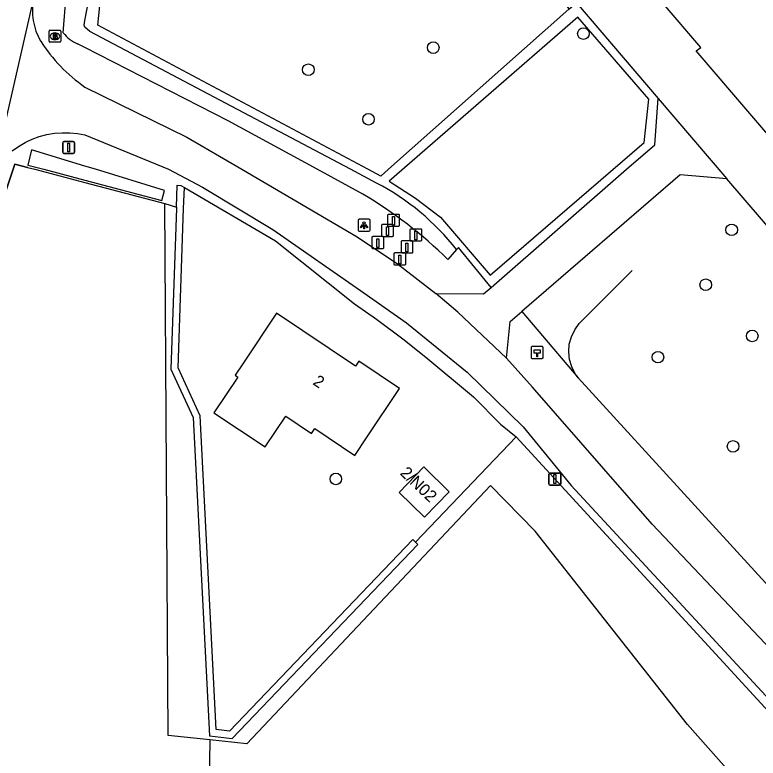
# Model space of a CAD drawing. Extents: x 160203 to 161526, y 379529 to 381797.
# Drawn here: x 160994.1 to 161056.6, y 381200.5 to 381263 of the extents above; entities that cross this region are included whole.
import ezdxf

# ---------------------------------------------------------------- set-up
doc = ezdxf.new("R2010")
doc.units = 0
for name, color, linetype in [('IMGEO_Boom', 7, 'Continuous'), ('IMGEO_Bouwland', 7, 'Continuous'), ('IMGEO_Brandkraan', 7, 'Continuous'), ('IMGEO_Grasland_agrarisch', 7, 'Continuous'), ('IMGEO_Grasland_overig', 7, 'Continuous'), ('IMGEO_Groenvoorziening', 7, 'Continuous'), ('IMGEO_Haag', 7, 'Continuous'), ('IMGEO_Hectometerpaal', 7, 'Continuous'), ('IMGEO_Hek', 7, 'Continuous'), ('IMGEO_Inrit_open', 7, 'Continuous'), ('IMGEO_Lichtpunt', 7, 'Continuous'), ('IMGEO_Loofbos', 7, 'Continuous'), ('IMGEO_Paal', 7, 'Continuous'), ('IMGEO_Pand', 7, 'Continuous'), ('IMGEO_Pand_nummerreeks', 7, 'Continuous'), ('IMGEO_Rijbaan_lokaal_gesloten', 7, 'Continuous'), ('IMGEO_Verkeersbordpaal', 7, 'Continuous'), ('IMGEO_Waterloop', 7, 'Continuous')]:
    doc.layers.add(name, color=color, linetype=linetype)

msp = doc.modelspace()

# ---------------------------------------------------------------- linework, layer by layer
at = {"layer": 'IMGEO_Boom'}
for centre in [(161041.928, 381261.416), (161029.301, 381260.235), (161018.79, 381258.378), (161023.851, 381254.21), (161054.398, 381244.908), (161052.216, 381240.288), (161056.13, 381235.981), (161048.198, 381234.197), (161054.516, 381226.691), (161021.103, 381223.95)]:
    msp.add_circle(centre, 0.489, dxfattribs=at)
at = {"layer": 'IMGEO_Bouwland'}
for points in [[(161010.972, 381081.302), (161010.953, 381074.647), (161003.548, 381076.227), (161000, 381077.092), (160995.21, 381078.26), (160994.378, 381077.678), (160975.971, 381079.297), (160943.925, 381083.756), (160939.305, 381085.021), (160993.954, 381250), (160994.1, 381250.44), (160995.157, 381250.162), (160995.774, 381250), (161000, 381248.889), (161006.713, 381247.124)], [(161010.514, 381202.004), (161010.411, 381196.554)]]:
    msp.add_lwpolyline(points, dxfattribs=at)
at = {"layer": 'IMGEO_Brandkraan'}
for p, q in [((160997.05, 381261.695), (160997.902, 381261.695)), ((160996.975, 381260.769), (160996.975, 381261.621)), ((160997.463, 381261.475), (160997.488, 381261.475)), ((160997.976, 381261.621), (160997.976, 381260.769)), ((160997.902, 381260.695), (160997.05, 381260.695)), ((160997.486, 381260.915), (160997.461, 381260.915))]:
    msp.add_line(p, q, dxfattribs=at)
for points in [[(160997.05, 381261.695), (160997.902, 381261.695)], [(160996.975, 381260.769), (160996.975, 381261.621)], [(160997.323, 381261.395), (160997.323, 381260.995), (160997.536, 381260.995)], [(160997.554, 381261.395), (160997.323, 381261.395)], [(160997.502, 381261.314), (160997.448, 381261.314), (160997.448, 381261.238)], [(160997.448, 381261.238), (160997.501, 381261.238)], [(160997.51, 381261.162), (160997.448, 381261.162), (160997.448, 381261.081)], [(160997.448, 381261.081), (160997.51, 381261.081)], [(160997.976, 381261.621), (160997.976, 381260.769)], [(160997.902, 381260.695), (160997.05, 381260.695)]]:
    msp.add_lwpolyline(points, dxfattribs=at)
for centre, radius, start, end in [((160997.052, 381261.619), 0.0765, 91.55205, 178.44795), ((160997.052, 381261.619), 0.0765, 91.55205, 178.44795), ((160997.9, 381261.619), 0.0765, 1.55205, 88.44795), ((160997.9, 381261.619), 0.0765, 1.55205, 88.44795), ((160997.503, 381261.276), 0.0379, 267.82845, 90.93552), ((160997.511, 381261.121), 0.0404, 269.87594, 90.50774), ((160997.558, 381261.25), 0.145, 59.4692, 91.53667), ((160997.583, 381261.297), 0.0922, 285.51372, 58.15012), ((160997.588, 381261.105), 0.105, 301.31148, 78.98903), ((160997.052, 381260.771), 0.0765, 181.55205, 268.44795), ((160997.052, 381260.771), 0.0765, 181.55205, 268.44795), ((160997.542, 381261.246), 0.251, 268.66757, 293.53466), ((160997.9, 381260.771), 0.0765, 271.55205, 358.44795), ((160997.9, 381260.771), 0.0765, 271.55205, 358.44795)]:
    msp.add_arc(centre, radius, start, end, dxfattribs=at)
for centre, major_axis, ratio, start_param, end_param in [((160997.462, 381261.195), (-0.387, 0.002), 0.722429, 4.712389, 7.853982), ((160997.487, 381261.195), (-0.39, 0.002), 0.717154, 1.570796, 4.712389)]:
    msp.add_ellipse(centre, major_axis=major_axis, ratio=ratio, start_param=start_param, end_param=end_param, dxfattribs=at)
at = {"layer": 'IMGEO_Grasland_agrarisch'}
msp.add_lwpolyline([(161040.704, 381263.465), (161025.539, 381250), (161024.88, 381249.415), (161023.785, 381250), (161001.07, 381262.141), (161001.418, 381265.417), (161003.032, 381274.033), (161003.367, 381284.915), (161005.086, 381286.001)], dxfattribs=at)
at = {"layer": 'IMGEO_Grasland_overig'}
msp.add_lwpolyline([(161036.736, 381238.047), (161041.491, 381232.447), (161060.216, 381211.973)], dxfattribs=at)
at = {"layer": 'IMGEO_Groenvoorziening'}
for points in [[(161040.704, 381263.465), (161041.339, 381264.007), (161048.214, 381255.953)], [(161047.031, 381252.253), (161047.443, 381255.899), (161041.46, 381262.811), (161025.599, 381249.008), (161027.816, 381247.584), (161029.904, 381245.979), (161034.072, 381241.099), (161047.031, 381252.253)], [(161081.374, 381241.599), (161083.542, 381239.045), (161074.732, 381231.273), (161073.023, 381233.247), (161069.952, 381230.624), (161053.998, 381249.187)], [(161008.358, 381248.475), (161016.014, 381243.993), (161022.676, 381238.69), (161024.528, 381237.381), (161026.738, 381235.726), (161028.679, 381234.184), (161032.692, 381230.87), (161034.943, 381228.573), (161036.267, 381227.494)], [(161034.16, 381240.067), (161031.419, 381243.429), (161031.254, 381243.257)]]:
    msp.add_lwpolyline(points, dxfattribs=at)
at = {"layer": 'IMGEO_Haag'}
for points in [[(161007.701, 381246.818), (161007.764, 381248.657), (161008.064, 381248.647), (161008.358, 381248.475)], [(161027.792, 381218.641), (161027.575, 381218.848), (161012.159, 381202.744), (161011.042, 381202.875), (161009.7, 381229.266), (161007.833, 381233.298), (161008.298, 381246.716), (161008.358, 381248.475)], [(161007.701, 381246.818), (161007.698, 381246.736), (161007.229, 381233.176), (161009.107, 381229.12), (161010.468, 381202.339), (161012.385, 381202.114), (161028.008, 381218.433), (161027.792, 381218.641)]]:
    msp.add_lwpolyline(points, dxfattribs=at)
at = {"layer": 'IMGEO_Hectometerpaal'}
for p, q in [((161037.533, 381235.009), (161037.533, 381234.168)), ((161037.533, 381235.009), (161037.533, 381234.168)), ((161038.449, 381235.093), (161037.608, 381235.093)), ((161038.449, 381235.093), (161037.608, 381235.093)), ((161038.533, 381234.177), (161038.533, 381235.018)), ((161038.533, 381234.177), (161038.533, 381235.018)), ((161037.617, 381234.093), (161038.458, 381234.093)), ((161037.617, 381234.093), (161038.458, 381234.093))]:
    msp.add_line(p, q, dxfattribs=at)
msp.add_lwpolyline([(161038.058, 381234.237), (161037.998, 381234.237), (161037.998, 381234.542), (161037.778, 381234.542), (161037.778, 381234.811), (161038.278, 381234.811), (161038.278, 381234.542), (161038.058, 381234.542), (161038.058, 381234.237)], dxfattribs=at)
for centre, start, end in [((161037.611, 381235.015), 92.4484, 184.28452), ((161037.611, 381235.015), 92.4484, 184.28452), ((161038.455, 381235.015), 2.4484, 94.28452), ((161038.455, 381235.015), 2.4484, 94.28452), ((161038.455, 381234.171), 272.4484, 4.28452), ((161038.455, 381234.171), 272.4484, 4.28452), ((161037.611, 381234.171), 182.4484, 274.28452), ((161037.611, 381234.171), 182.4484, 274.28452)]:
    msp.add_arc(centre, 0.0779, start, end, dxfattribs=at)
at = {"layer": 'IMGEO_Hek'}
for points in [[(161024.88, 381249.415), (161023.785, 381250), (161001.07, 381262.141), (161001.418, 381265.417), (161003.032, 381274.033), (161003.367, 381284.915), (161005.086, 381286.001)], [(161041.952, 381266.885), (161039.801, 381264.963), (161040.704, 381263.465), (161025.539, 381250), (161024.88, 381249.415)], [(160995.157, 381250.162), (160994.1, 381250.44), (160993.954, 381250), (160939.305, 381085.021), (160943.925, 381083.756), (160975.971, 381079.297), (160994.378, 381077.678), (160995.21, 381078.26), (161000, 381077.092), (161003.548, 381076.227), (161010.953, 381074.647)], [(161008.064, 381248.647), (161008.358, 381248.475), (161016.014, 381243.993), (161022.676, 381238.69), (161024.528, 381237.381), (161026.738, 381235.726), (161028.679, 381234.184), (161032.692, 381230.87), (161034.943, 381228.573), (161036.267, 381227.494)], [(161041.491, 381232.447), (161041.237, 381232.798), (161040.941, 381233.375), (161040.757, 381233.997), (161040.69, 381234.642), (161040.742, 381235.288), (161040.913, 381235.914), (161041.196, 381236.497), (161041.581, 381237.019), (161046.025, 381241.49)], [(161036.267, 381227.494), (161059.702, 381201.99), (161062.8, 381198.618), (161073.827, 381188.007), (161074.485, 381187.273), (161075.831, 381185.995), (161077.303, 381184.864), (161078.885, 381183.893), (161080.56, 381183.093), (161082.31, 381182.472), (161085.055, 381181.736)]]:
    msp.add_lwpolyline(points, dxfattribs=at)
at = {"layer": 'IMGEO_Inrit_open'}
for points in [[(161034.16, 381240.067), (161045.56, 381250), (161047.935, 381252.069), (161048.214, 381255.953)], [(161048.214, 381255.953), (161053.998, 381249.187)], [(161053.998, 381249.187), (161050.077, 381249.546), (161036.736, 381238.047)], [(161029.512, 381239.55), (161033.525, 381239.513), (161034.16, 381240.067)], [(161035.453, 381234.099), (161035.763, 381237.208), (161036.736, 381238.047)]]:
    msp.add_lwpolyline(points, dxfattribs=at)
at = {"layer": 'IMGEO_Lichtpunt'}
for p, q in [((161022.983, 381245.698), (161022.983, 381244.891)), ((161022.983, 381245.698), (161022.983, 381244.891)), ((161023.885, 381245.793), (161023.077, 381245.793)), ((161023.885, 381245.793), (161023.077, 381245.793)), ((161023.979, 381244.891), (161023.979, 381245.698)), ((161023.979, 381244.891), (161023.979, 381245.698)), ((161023.077, 381244.797), (161023.885, 381244.797)), ((161023.077, 381244.797), (161023.885, 381244.797))]:
    msp.add_line(p, q, dxfattribs=at)
for points in [[(161023.357, 381245.362), (161023.396, 381245.334), (161023.208, 381245.072), (161023.17, 381245.099), (161023.357, 381245.362)], [(161023.459, 381245.314), (161023.506, 381245.314), (161023.506, 381244.992), (161023.459, 381244.992), (161023.459, 381245.314)], [(161023.569, 381245.334), (161023.607, 381245.361), (161023.794, 381245.099), (161023.755, 381245.071), (161023.569, 381245.334)]]:
    msp.add_lwpolyline(points, dxfattribs=at)
msp.add_circle((161023.482, 381245.496), 0.0994, dxfattribs=at)
for centre, start, end in [((161023.077, 381245.698), 90, 180), ((161023.077, 381245.698), 90, 180), ((161023.885, 381245.698), 0, 90), ((161023.885, 381245.698), 0, 90), ((161023.077, 381244.891), 180, 270), ((161023.077, 381244.891), 180, 270), ((161023.885, 381244.891), 270, 0), ((161023.885, 381244.891), 270, 360)]:
    msp.add_arc(centre, 0.0946, start, end, dxfattribs=at)
at = {"layer": 'IMGEO_Loofbos'}
for points in [[(161006.713, 381247.124), (161007.701, 381246.818)], [(161010.514, 381202.004), (161007.008, 381202.372), (161006.713, 381247.124)], [(161036.267, 381227.494), (161027.792, 381218.641)], [(161036.267, 381227.494), (161059.702, 381201.99), (161062.8, 381198.618), (161073.827, 381188.007), (161074.485, 381187.273), (161075.831, 381185.995), (161077.303, 381184.864), (161078.885, 381183.893), (161080.56, 381183.093), (161082.31, 381182.472), (161085.055, 381181.736)], [(161082.58, 381175.752), (161077.672, 381178.299), (161070.576, 381182.79), (161061.577, 381191.025), (161050.681, 381203.282), (161037.868, 381219.565), (161034.126, 381223.392), (161013.621, 381201.677), (161010.514, 381202.004)]]:
    msp.add_lwpolyline(points, dxfattribs=at)
at = {"layer": 'IMGEO_Paal'}
for p, q in [((161025.454, 381246.125), (161025.454, 381245.284)), ((161025.454, 381246.125), (161025.454, 381245.284)), ((161026.37, 381246.209), (161025.529, 381246.209)), ((161026.37, 381246.209), (161025.529, 381246.209)), ((161026.454, 381245.293), (161026.454, 381246.134)), ((161026.454, 381245.293), (161026.454, 381246.134)), ((161024.95, 381245.276), (161024.95, 381244.435)), ((161024.95, 381245.276), (161024.95, 381244.435)), ((161025.866, 381245.36), (161025.025, 381245.36)), ((161025.866, 381245.36), (161025.025, 381245.36)), ((161025.538, 381245.209), (161026.379, 381245.209)), ((161025.538, 381245.209), (161026.379, 381245.209)), ((161025.95, 381244.444), (161025.95, 381245.285)), ((161025.95, 381244.444), (161025.95, 381245.285)), ((161027.335, 381244.893), (161027.335, 381244.052)), ((161027.335, 381244.893), (161027.335, 381244.052)), ((161028.251, 381244.977), (161027.41, 381244.977)), ((161028.251, 381244.977), (161027.41, 381244.977)), ((161028.335, 381244.061), (161028.335, 381244.902)), ((161028.335, 381244.061), (161028.335, 381244.902)), ((161024.135, 381244.256), (161024.135, 381243.415)), ((161024.135, 381244.256), (161024.135, 381243.415)), ((161025.051, 381244.34), (161024.21, 381244.34)), ((161025.051, 381244.34), (161024.21, 381244.34)), ((161025.034, 381244.36), (161025.875, 381244.36)), ((161025.034, 381244.36), (161025.875, 381244.36)), ((161025.135, 381243.424), (161025.135, 381244.265)), ((161025.135, 381243.424), (161025.135, 381244.265)), ((161026.588, 381243.893), (161026.588, 381243.052)), ((161026.588, 381243.893), (161026.588, 381243.052)), ((161027.504, 381243.977), (161026.663, 381243.977)), ((161027.504, 381243.977), (161026.663, 381243.977)), ((161027.419, 381243.977), (161028.26, 381243.977)), ((161027.419, 381243.977), (161028.26, 381243.977)), ((161027.588, 381243.061), (161027.588, 381243.902)), ((161027.588, 381243.061), (161027.588, 381243.902)), ((161024.219, 381243.34), (161025.06, 381243.34)), ((161024.219, 381243.34), (161025.06, 381243.34)), ((161026.901, 381242.961), (161026.06, 381242.961)), ((161026.901, 381242.961), (161026.06, 381242.961)), ((161026.672, 381242.977), (161027.513, 381242.977)), ((161026.672, 381242.977), (161027.513, 381242.977)), ((161025.985, 381242.877), (161025.985, 381242.036)), ((161025.985, 381242.877), (161025.985, 381242.036)), ((161026.985, 381242.045), (161026.985, 381242.886)), ((161026.985, 381242.045), (161026.985, 381242.886)), ((161026.069, 381241.961), (161026.91, 381241.961)), ((161026.069, 381241.961), (161026.91, 381241.961))]:
    msp.add_line(p, q, dxfattribs=at)
for points in [[(161025.869, 381246.022), (161026.029, 381246.022), (161026.029, 381245.289), (161025.869, 381245.289), (161025.869, 381246.022)], [(161025.365, 381245.173), (161025.525, 381245.173), (161025.525, 381244.44), (161025.365, 381244.44), (161025.365, 381245.173)], [(161027.75, 381244.79), (161027.91, 381244.79), (161027.91, 381244.057), (161027.75, 381244.057), (161027.75, 381244.79)], [(161024.55, 381244.153), (161024.71, 381244.153), (161024.71, 381243.42), (161024.55, 381243.42), (161024.55, 381244.153)], [(161027.003, 381243.79), (161027.163, 381243.79), (161027.163, 381243.057), (161027.003, 381243.057), (161027.003, 381243.79)], [(161026.4, 381242.774), (161026.56, 381242.774), (161026.56, 381242.041), (161026.4, 381242.041), (161026.4, 381242.774)]]:
    msp.add_lwpolyline(points, dxfattribs=at)
for centre, start, end in [((161025.532, 381246.131), 92.4484, 184.28452), ((161025.532, 381246.131), 92.4484, 184.28452), ((161026.376, 381246.131), 2.4484, 94.28452), ((161026.376, 381246.131), 2.4484, 94.28452), ((161025.028, 381245.282), 92.4484, 184.28452), ((161025.028, 381245.282), 92.4484, 184.28452), ((161025.532, 381245.287), 182.4484, 274.28452), ((161025.532, 381245.287), 182.4484, 274.28452), ((161025.872, 381245.282), 2.4484, 94.28452), ((161025.872, 381245.282), 2.4484, 94.28452), ((161026.376, 381245.287), 272.4484, 4.28452), ((161026.376, 381245.287), 272.4484, 4.28452), ((161027.413, 381244.899), 92.4484, 184.28452), ((161027.413, 381244.899), 92.4484, 184.28452), ((161028.257, 381244.899), 2.4484, 94.28452), ((161028.257, 381244.899), 2.4484, 94.28452), ((161024.213, 381244.262), 92.4484, 184.28452), ((161024.213, 381244.262), 92.4484, 184.28452), ((161025.028, 381244.438), 182.4484, 274.28452), ((161025.028, 381244.438), 182.4484, 274.28452), ((161025.057, 381244.262), 2.4484, 94.28452), ((161025.057, 381244.262), 2.4484, 94.28452), ((161025.872, 381244.438), 272.4484, 4.28452), ((161025.872, 381244.438), 272.4484, 4.28452), ((161026.666, 381243.899), 92.4484, 184.28452), ((161026.666, 381243.899), 92.4484, 184.28452), ((161027.413, 381244.055), 182.4484, 274.28452), ((161027.413, 381244.055), 182.4484, 274.28452), ((161027.51, 381243.899), 2.4484, 94.28452), ((161027.51, 381243.899), 2.4484, 94.28452), ((161028.257, 381244.055), 272.4484, 4.28452), ((161028.257, 381244.055), 272.4484, 4.28452), ((161024.213, 381243.418), 182.4484, 274.28452), ((161024.213, 381243.418), 182.4484, 274.28452), ((161025.057, 381243.418), 272.4484, 4.28452), ((161025.057, 381243.418), 272.4484, 4.28452), ((161026.063, 381242.883), 92.4484, 184.28452), ((161026.063, 381242.883), 92.4484, 184.28452), ((161026.666, 381243.055), 182.4484, 274.28452), ((161026.666, 381243.055), 182.4484, 274.28452), ((161026.907, 381242.883), 2.4484, 94.28452), ((161026.907, 381242.883), 2.4484, 94.28452), ((161027.51, 381243.055), 272.4484, 4.28452), ((161027.51, 381243.055), 272.4484, 4.28452), ((161026.063, 381242.039), 182.4484, 274.28452), ((161026.063, 381242.039), 182.4484, 274.28452), ((161026.907, 381242.039), 272.4484, 4.28452), ((161026.907, 381242.039), 272.4484, 4.28452)]:
    msp.add_arc(centre, 0.0779, start, end, dxfattribs=at)
at = {"layer": 'IMGEO_Pand'}
for points in [[(161081.374, 381241.599), (161080.583, 381240.923), (161082.106, 381239.134), (161074.809, 381232.682), (161059.945, 381250), (161051.402, 381259.954), (161051.802, 381260.257), (161048.632, 381263.954), (161054.293, 381268.751), (161057.435, 381265.037), (161058.22, 381265.701), (161071.802, 381250), (161074.813, 381246.519), (161075.343, 381247.046), (161077.319, 381244.777), (161078.044, 381245.396)], [(161023.694, 381227.402), (161026.468, 381231.561), (161023.028, 381233.855), (161022.757, 381233.448), (161016.101, 381237.888), (161013.327, 381233.729), (161012.626, 381232.678), (161012.854, 381232.526), (161010.851, 381229.522), (161015.162, 381226.647), (161016.883, 381229.228), (161019.056, 381227.779), (161019.33, 381228.19), (161022.714, 381225.933), (161023.694, 381227.402)], [(161028.562, 381220.734), (161030.645, 381222.879), (161028.504, 381224.959), (161026.417, 381222.818), (161028.562, 381220.734)]]:
    msp.add_lwpolyline(points, dxfattribs=at)
at = {"layer": 'IMGEO_Rijbaan_lokaal_gesloten'}
for points in [[(160992.397, 381250), (160995.644, 381264.144), (160995.701, 381264.365)], [(161000, 381256.922), (161008.561, 381252.716), (161013.194, 381250), (161022.904, 381244.308), (161026.29, 381242.043), (161029.512, 381239.55)], [(160993.876, 381251.557), (160994.405, 381251.932), (160994.964, 381252.258), (160995.199, 381252.368), (160995.551, 381252.533), (160996.16, 381252.755), (160996.786, 381252.921), (160997.425, 381253.031), (160998.071, 381253.083), (160998.719, 381253.077), (160999.363, 381253.014), (161000, 381252.893), (161007.017, 381250), (161009.875, 381248.512), (161015.8, 381244.93), (161023.448, 381239.603), (161027.05, 381237.09), (161032.145, 381232.938), (161036.849, 381228.347), (161040.903, 381223.397), (161062.517, 381200.044)], [(161035.453, 381234.099), (161031.365, 381237.996), (161029.512, 381239.55)], [(161057.71, 381209.573), (161047.699, 381220.155), (161037.654, 381231.685), (161035.453, 381234.099)]]:
    msp.add_lwpolyline(points, dxfattribs=at)
for centre, radius, start, end in [((161000.522, 381263.304), 4.937, 167.58722, 210.59833), ((161007.657, 381268.027), 13.489, 212.44316, 235.41491)]:
    msp.add_arc(centre, radius, start, end, dxfattribs=at)
at = {"layer": 'IMGEO_Verkeersbordpaal'}
for p, q in [((160998.224, 381252.333), (160999.014, 381252.333)), ((160999.014, 381252.333), (160998.224, 381252.333)), ((160998.124, 381251.433), (160998.124, 381252.233)), ((160998.124, 381252.233), (160998.124, 381251.433)), ((160999.114, 381252.233), (160999.114, 381251.433)), ((160999.114, 381251.433), (160999.114, 381252.233)), ((160999.014, 381251.333), (160998.224, 381251.333)), ((160998.224, 381251.333), (160999.014, 381251.333)), ((161039.032, 381223.54), (161039.032, 381224.34)), ((161039.032, 381224.34), (161039.032, 381223.54)), ((161039.132, 381224.44), (161039.922, 381224.44)), ((161039.922, 381224.44), (161039.132, 381224.44)), ((161040.022, 381224.34), (161040.022, 381223.54)), ((161040.022, 381223.54), (161040.022, 381224.34)), ((161039.922, 381223.44), (161039.132, 381223.44)), ((161039.132, 381223.44), (161039.922, 381223.44))]:
    msp.add_line(p, q, dxfattribs=at)
for points in [[(160998.544, 381252.208), (160998.694, 381252.208), (160998.694, 381251.458), (160998.544, 381251.458), (160998.544, 381252.208)], [(161039.452, 381224.315), (161039.602, 381224.315), (161039.602, 381223.565), (161039.452, 381223.565), (161039.452, 381224.315)]]:
    msp.add_lwpolyline(points, dxfattribs=at)
for centre, start, end in [((160998.224, 381252.233), 90, 180), ((160998.224, 381252.233), 90, 180), ((160999.014, 381252.233), 0, 90), ((160999.014, 381252.233), 360, 90), ((160998.224, 381251.433), 180, 270), ((160998.224, 381251.433), 180, 270), ((160999.014, 381251.433), 270, 0), ((160999.014, 381251.433), 270, 0), ((161039.132, 381224.34), 90, 180), ((161039.132, 381224.34), 90, 180), ((161039.922, 381224.34), 0, 90), ((161039.922, 381224.34), 360, 90), ((161039.132, 381223.54), 180, 270), ((161039.132, 381223.54), 180, 270), ((161039.922, 381223.54), 270, 0), ((161039.922, 381223.54), 270, 0)]:
    msp.add_arc(centre, 0.1, start, end, dxfattribs=at)
at = {"layer": 'IMGEO_Waterloop'}
for points in [[(160998.171, 381261.477), (160998.935, 381270.922), (161000, 381281.419), (161002.554, 381285.006)], [(161024.534, 381248.833), (161022.327, 381250), (161000.404, 381261.592), (161000, 381261.97), (160999.924, 381262.133), (161000, 381262.526), (161002.129, 381273.543), (161002.341, 381280.604), (161002.554, 381285.006)], [(161023.378, 381247.917), (161019.539, 381250), (161012.044, 381254.067), (161000, 381260.241), (160999.364, 381260.567)], [(161000.876, 381250), (161000, 381250.267), (160995.496, 381251.641), (160995.201, 381250.356), (160996.552, 381250), (161000, 381249.091), (161006.458, 381247.388), (161006.688, 381248.227), (161000.876, 381250)], [(161031.254, 381243.257), (161030.535, 381242.417)]]:
    msp.add_lwpolyline(points, dxfattribs=at)
for centre, radius, start, end in [((161000.584, 381263.403), 3.088, 218.60193, 246.72653), ((161014.958, 381230.455), 20.723, 38.15274, 62.47807), ((161003.613, 381214.791), 38.575, 45.73969, 59.17731)]:
    msp.add_arc(centre, radius, start, end, dxfattribs=at)

# ---------------------------------------------------------------- texts
at = {"layer": 'IMGEO_Pand_nummerreeks'}
for s, rotation, p in [('2', 326.29404, (161019.097, 381231.945)), ('2/N02', 316.32872, (161026.441, 381224.375))]:
    msp.add_text(s, height=1, rotation=rotation, dxfattribs=at).set_placement(p)

doc.saveas('drawing.dxf')
